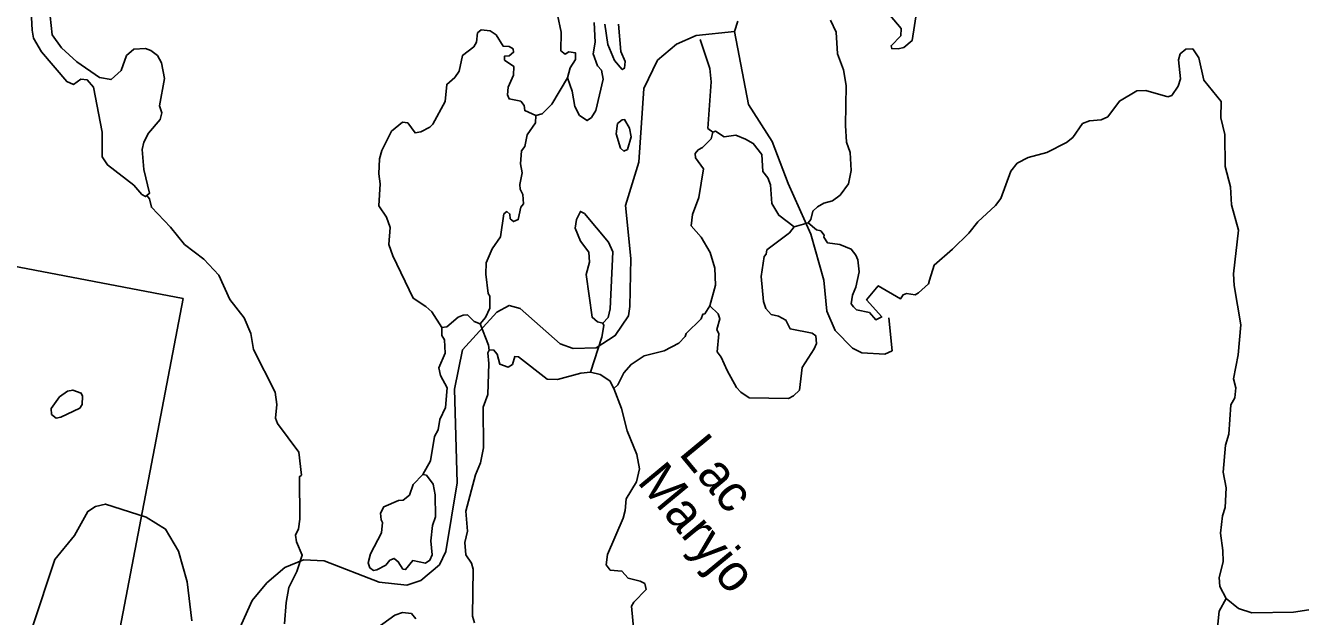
# Model space of a CAD drawing. Extents: x 347312 to 350503, y 6073086 to 6076432.
# Drawn here: x 349676.6 to 349803.4, y 6073953.1 to 6074011.8 of the extents above; entities that cross this region are included whole.
import ezdxf

# ---------------------------------------------------------------- set-up
doc = ezdxf.new("R2010")
doc.units = 0
doc.layers.add('Level 63', color=7, linetype='Continuous')

msp = doc.modelspace()

# ---------------------------------------------------------------- linework, layer by layer
at = {"layer": 'Level 63'}
for p, q in [((349747.4, 6074012.26), (349747.07, 6074011.24)), ((349752.98, 6073991.83), (349754.39, 6073992.24))]:
    msp.add_line(p, q, dxfattribs=at)
for points in [[(349677.13, 6074014.56), (349677.27, 6074011.36), (349677.42, 6074010.56), (349678.21, 6074009.22), (349680.71, 6074006.27), (349681.37, 6074005.98), (349682.1, 6074006.5), (349682.75, 6074006.42), (349683.37, 6074005.71), (349684.24, 6074001.25), (349684.25, 6073998.77), (349684.77, 6073997.98), (349687.38, 6073995.98), (349688.18, 6073995.04), (349688.55, 6073994.84), (349688.68, 6073994.95)], [(349765.18, 6074013.31), (349764.71, 6074010.33), (349763.9, 6074009.64), (349763.31, 6074009.5), (349762.68, 6074009.54), (349762.62, 6074009.82), (349763.58, 6074010.8), (349763.61, 6074011.52), (349760.5, 6074015.24)], [(349688.68, 6073994.95), (349688.95, 6073995.16), (349688.38, 6073997.53), (349688.22, 6073999.51), (349688.39, 6074000.25), (349688.83, 6074001.14), (349689.99, 6074002.49), (349690.16, 6074003.16), (349689.94, 6074003.86), (349690.44, 6074006.58), (349690.13, 6074008.13), (349689.73, 6074008.85), (349689.06, 6074009.35), (349688.54, 6074009.53), (349687.38, 6074009.48), (349686.64, 6074008.84), (349686.13, 6074007.36), (349685.12, 6074006.45), (349683.97, 6074006.67), (349681.72, 6074008.21), (349680.19, 6074009.6), (349679.28, 6074010.89), (349678.97, 6074013.68)], [(349729.49, 6074012.9), (349729.83, 6074011.16), (349729.82, 6074009.32), (349730.24, 6074008.99), (349730.6, 6074009.23), (349731.28, 6074009.11), (349731.27, 6074008.45), (349730.72, 6074007.64)], [(349730.72, 6074007.64), (349730.48, 6074006.63), (349730.93, 6074005.31), (349731.21, 6074003.79), (349731.65, 6074002.89), (349732.44, 6074002.38), (349732.84, 6074002.69), (349733.28, 6074003.37), (349734.01, 6074006.5), (349733.84, 6074007.39), (349733.44, 6074007.83), (349733.03, 6074009.03), (349733.22, 6074010.16), (349733.12, 6074012.14)], [(349734.19, 6074011.96), (349734.47, 6074009.95), (349735.13, 6074008.36), (349735.91, 6074007.45), (349736.13, 6074007.58), (349736.21, 6074008.24), (349735.78, 6074009.26), (349735.55, 6074011.95)], [(349756.59, 6074012.37), (349757.15, 6074011.18), (349757.29, 6074009.02), (349757.89, 6074007.43), (349758.16, 6074005.86), (349758.09, 6074001.9), (349758.2, 6074000.25), (349758.54, 6073999.21), (349758.66, 6073997.41), (349758.39, 6073996.11), (349757.56, 6073994.96), (349756.8, 6073994.42), (349755.95, 6073994.18)], [(349747.07, 6074011.24), (349743.27, 6074010.84), (349741.29, 6074009.98), (349739.41, 6074008.38), (349738.05, 6074005.57), (349737.56, 6073998.24), (349736.24, 6073993.94), (349736.75, 6073988.7), (349736.67, 6073983.92), (349736.53, 6073983), (349735.22, 6073981.03), (349733.31, 6073979.8), (349731.04, 6073979.74), (349729.73, 6073980.22), (349725.78, 6073983.71), (349724.66, 6073984.02), (349723.46, 6073983.35), (349720.03, 6073979.6), (349719.24, 6073975.72), (349719.51, 6073966.39), (349718.39, 6073959.59), (349717.75, 6073958.27), (349715.9, 6073956.7), (349714.51, 6073956.25), (349711.76, 6073956.52), (349706.28, 6073958.64), (349704.24, 6073958.76), (349702.39, 6073958), (349700.58, 6073956.46), (349699.13, 6073954.72), (349697.49, 6073951.03)], [(349721.2, 6073982.43), (349721.78, 6073982.18), (349722.31, 6073982.81), (349722.75, 6073983.76), (349722.74, 6073984.94), (349722.59, 6073985.2), (349722.36, 6073987.14), (349722.4, 6073988.26), (349722.98, 6073989.64), (349723.82, 6073990.85), (349724.15, 6073993.11), (349724.45, 6073993.35), (349724.75, 6073993.1), (349724.79, 6073992.64), (349725.12, 6073992.36), (349725.57, 6073992.55), (349725.83, 6073993.79), (349726.11, 6073994.12), (349726.04, 6073995.04), (349725.77, 6073995.58), (349725.73, 6073996.04), (349725.96, 6073997.2), (349725.79, 6073998.1), (349725.91, 6073999.38), (349726.23, 6073999.8), (349726.46, 6074000.96), (349727.29, 6074002.16), (349727.32, 6074002.88), (349726.22, 6074003.38), (349726.16, 6074003.87), (349725.82, 6074004.3), (349724.66, 6074004.53), (349724.5, 6074004.94), (349724.56, 6074005.69), (349725.12, 6074006.9), (349725.13, 6074007.77), (349724.2, 6074008.4), (349724.22, 6074008.79), (349724.68, 6074008.83), (349725.11, 6074009.17), (349725.06, 6074009.51), (349724.66, 6074009.74), (349724.09, 6074009.77), (349723.37, 6074010.89), (349722.79, 6074011.29), (349721.89, 6074011.39), (349721.52, 6074011.1), (349721.44, 6074010.17), (349721.15, 6074009.72), (349720.05, 6074008.85), (349719.71, 6074007.29), (349719.28, 6074006.67), (349718.47, 6074005.98), (349718.3, 6074004.27), (349717.1, 6074002.02), (349716.79, 6074001.72), (349715.89, 6074001.28), (349715.33, 6074001.16), (349714.6, 6074002.16), (349714.06, 6074002.22), (349712.99, 6074001.32), (349712.01, 6073999.4), (349711.79, 6073998.58), (349711.71, 6073997.1), (349711.86, 6073996.09), (349711.73, 6073993.92), (349712.48, 6073992.78), (349712.84, 6073991.76), (349712.71, 6073990.08), (349713.12, 6073988.94), (349715.14, 6073984.74), (349716.38, 6073983.93), (349716.98, 6073983.38), (349717.98, 6073981.83), (349718.48, 6073981.9), (349719.62, 6073982.86), (349720.1, 6073983.07), (349720.52, 6073983.08), (349721.2, 6073982.43)], [(349747.07, 6074011.24), (349748.46, 6074003.99), (349750.79, 6074000.3), (349752.39, 6073996.14)], [(349743.64, 6074010.43), (349744.61, 6074007.56), (349744.73, 6074006.24), (349744.43, 6074001.61), (349744.9, 6074001.23)], [(349790.13, 6074004.73), (349790.51, 6074004.87), (349791.14, 6074005.79), (349791.37, 6074006.52), (349791.17, 6074008.42), (349791.36, 6074009.01), (349791.9, 6074009.49), (349792.6, 6074009.5), (349793.19, 6074008.61), (349793.69, 6074006.4), (349795.41, 6074004.29), (349795.4, 6074002.66), (349795.79, 6074001.01), (349795.81, 6073997.83), (349796.33, 6073995.8), (349796.45, 6073994), (349797.13, 6073991.49), (349796.65, 6073987.16), (349796.7, 6073986), (349797.36, 6073982.08), (349797.11, 6073979.11), (349796.65, 6073976.74), (349796.88, 6073975.84), (349796.79, 6073974.85), (349796.38, 6073974.14), (349796.19, 6073971.22), (349795.85, 6073970.14), (349795.63, 6073967.47), (349795.9, 6073965.89), (349795.82, 6073963.94), (349795.54, 6073963.12), (349795.34, 6073961.39), (349795.6, 6073959.69), (349795.62, 6073958.57), (349795.22, 6073957.01), (349795.27, 6073956.12), (349795.92, 6073954.9), (349797.13, 6073953.91), (349798.45, 6073953.48), (349802.61, 6073953.57), (349804.12, 6073953.79)], [(349730.48, 6074006.63), (349728.93, 6074004), (349727.94, 6074003.05), (349727.32, 6074002.88)], [(349755.95, 6073994.18), (349755.3, 6073993.83), (349754.83, 6073993.4), (349754.64, 6073992.55), (349754.39, 6073992.24), (349755.22, 6073991.54), (349755.63, 6073991.43), (349755.97, 6073991), (349755.95, 6073990.82), (349756.31, 6073990.23), (349757.53, 6073990.06), (349758.66, 6073989.6), (349759.11, 6073989.03), (349759.32, 6073988.55), (349759.45, 6073987.35), (349759.13, 6073985.85), (349758.79, 6073985.04), (349758.66, 6073984.17), (349758.9, 6073983.87), (349759.17, 6073983.6), (349760.47, 6073983.33), (349761.11, 6073982.59), (349761.69, 6073982.88), (349760.19, 6073984.57), (349761.35, 6073985.98), (349763.57, 6073984.69), (349763.82, 6073985.06), (349764.14, 6073985.2), (349765, 6073985.07), (349765.33, 6073985.27), (349766.34, 6073986.18), (349766.45, 6073986.54), (349766.89, 6073988.03), (349768.74, 6073989.6), (349770.35, 6073991.2), (349771.24, 6073992.34), (349773.01, 6073993.95), (349773.54, 6073994.64), (349774.53, 6073997.37), (349775.16, 6073998.15), (349776.23, 6073998.72), (349778.1, 6073999.23), (349780.04, 6074000.21), (349780.67, 6074000.71), (349781.65, 6074002.08), (349782.35, 6074002.37), (349783.48, 6074002.45), (349784.15, 6074002.76), (349785.3, 6074004.32), (349787.05, 6074005.33), (349787.94, 6074005.38), (349790.13, 6074004.73)], [(349736.62, 6074001.62), (349736.14, 6074002.49), (349735.9, 6074002.46), (349735.43, 6074002.09), (349735.31, 6074001.07), (349735.75, 6073999.63), (349736.08, 6073999.35), (349736.43, 6073999.52), (349736.79, 6074000.78), (349736.62, 6074001.62)], [(349744.61, 6073983.97), (349745.43, 6073983.2), (349745.62, 6073982.7), (349745.31, 6073981.64), (349745.5, 6073981.2), (349745.35, 6073979.4), (349745.75, 6073978.9), (349746.32, 6073977.56), (349747.27, 6073975.87), (349747.7, 6073975.4), (349748.52, 6073974.85), (349752.42, 6073974.79), (349752.93, 6073975.03), (349753.51, 6073975.6), (349753.77, 6073977.87), (349754.99, 6073979.7), (349755.2, 6073980.25), (349755.14, 6073981.01), (349754.78, 6073981.27), (349752.59, 6073981.7), (349752.17, 6073982.57), (349751.43, 6073982.96), (349750.69, 6073983.13), (349750.19, 6073983.71), (349749.96, 6073984.4), (349749.71, 6073986.91), (349750, 6073988.88), (349750.21, 6073989.1), (349750.29, 6073989.54), (349752.52, 6073991.25), (349752.98, 6073991.83), (349751.48, 6073992.98), (349750.77, 6073994.15), (349750.65, 6073996.01), (349750.37, 6073996.71), (349749.87, 6073997.34), (349749.79, 6073999.02), (349748.92, 6074000.12), (349748.15, 6074000.54), (349747.2, 6074000.93), (349746.03, 6074000.76), (349745.19, 6074001.34), (349744.9, 6074001.23), (349744.76, 6074000.58), (349743.88, 6073999.71), (349743.46, 6073999.49), (349743.17, 6073999.1), (349743.18, 6073998.67), (349743.99, 6073997.58), (349743.51, 6073994.76), (349742.89, 6073993.07), (349742.76, 6073991.94), (349743.75, 6073990.82), (349744.63, 6073989.29), (349745.11, 6073987.72), (349745.16, 6073986.02), (349744.61, 6073983.97)], [(349680.34, 6073922.31), (349692.28, 6073984.7), (349619.96, 6073998.53), (349601.59, 6073902.48), (349673.91, 6073888.65), (349677.31, 6073906.44)], [(349752.39, 6073996.14), (349754.65, 6073991.09), (349755.94, 6073986.52), (349756.24, 6073983.46), (349757.05, 6073981.54), (349758.78, 6073979.77), (349759.73, 6073979.32), (349762.01, 6073979.18), (349762.72, 6073979.52), (349762.41, 6073982.8)], [(349688.68, 6073994.95), (349688.95, 6073994.61), (349689.12, 6073993.78), (349691.01, 6073991.8), (349692.42, 6073990.09), (349694.34, 6073988.62), (349695.82, 6073987.03), (349696.92, 6073984.6), (349698.35, 6073982.79), (349698.99, 6073981.24), (349699.28, 6073979.63), (349701.43, 6073975.41), (349701.58, 6073974.18), (349701.46, 6073972.83), (349701.67, 6073972.29), (349703.76, 6073969.44), (349704.04, 6073967.17), (349703.84, 6073967.01), (349703.86, 6073962.8), (349703.75, 6073961.84), (349703.43, 6073961.21), (349703.54, 6073960.53), (349704.11, 6073959.2), (349703.59, 6073957.59), (349702.79, 6073955.99), (349702.53, 6073954.53), (349702.34, 6073952.38)], [(349733.97, 6073982.27), (349734.51, 6073982.81), (349734.7, 6073983.67), (349734.98, 6073989.36), (349734.54, 6073990.32), (349732.15, 6073993.14), (349731.75, 6073993.37), (349731.35, 6073992.57), (349731.22, 6073991.71), (349731.77, 6073990.4), (349732.58, 6073989.31), (349732.64, 6073988.33), (349732.32, 6073987.1), (349732.91, 6073982.85), (349733.44, 6073982.39), (349733.97, 6073982.27)], [(349744.61, 6073983.97), (349744.13, 6073983.2), (349743.91, 6073983.14), (349743.74, 6073982.68), (349742.27, 6073981.24), (349742.17, 6073980.95), (349741.52, 6073980.27), (349740.06, 6073979.5), (349738.1, 6073979.03), (349736.79, 6073978.16), (349736.08, 6073977.33), (349735.46, 6073976.13), (349735.09, 6073975.78)], [(349717.98, 6073981.83), (349717.98, 6073981.02), (349718.24, 6073980.62), (349718.32, 6073979.28), (349717.7, 6073977.81), (349717.85, 6073977.07), (349718.5, 6073975.84), (349718.36, 6073973.89), (349717.79, 6073972.68), (349717.62, 6073971.67), (349717.27, 6073971.02), (349716.86, 6073968.58), (349716.1, 6073967.22)], [(349721.78, 6073982.18), (349722.63, 6073980.08), (349722.69, 6073979.59)], [(349733.97, 6073982.27), (349734.09, 6073982.04), (349733.89, 6073980.86), (349732.76, 6073977.41)], [(349732.76, 6073977.41), (349731.78, 6073977.29), (349729.46, 6073976.65), (349728.44, 6073976.71), (349725.61, 6073978.92), (349725.25, 6073978.96), (349725.01, 6073978.17), (349724.58, 6073977.88), (349723.74, 6073978.2), (349723.49, 6073979.19), (349723.11, 6073979.6), (349722.69, 6073979.59), (349722.57, 6073979.33), (349722.66, 6073978.26), (349722.54, 6073975.19), (349722.09, 6073973.91), (349722.13, 6073969.87), (349721.84, 6073968.39), (349721.33, 6073967.18), (349720.37, 6073963.6), (349720.53, 6073961.61), (349720.28, 6073960.49), (349720.38, 6073959.26), (349720.94, 6073958.41), (349721.09, 6073957.82), (349721.03, 6073953.16), (349721.22, 6073952.5)], [(349737.06, 6073951.68), (349736.83, 6073954.16), (349737.06, 6073954.56), (349738.3, 6073955.81), (349738.15, 6073956.4), (349737.7, 6073956.64), (349736.49, 6073956.93), (349735.88, 6073957.64), (349734.71, 6073957.74), (349734.31, 6073958.24), (349734.46, 6073959.29), (349736, 6073962.89), (349736.21, 6073963.65), (349736.29, 6073964.8), (349737.33, 6073966.49), (349737.61, 6073967.79), (349737.35, 6073969.22), (349736.41, 6073971.57), (349735.85, 6073973.78), (349735.09, 6073975.78), (349734.66, 6073976.53), (349733.73, 6073977.15), (349732.76, 6073977.41)], [(349682.27, 6073975.01), (349682.15, 6073975.3), (349681.31, 6073975.61), (349680.78, 6073975.52), (349679.99, 6073974.94), (349679.16, 6073973.8), (349679.21, 6073973.19), (349679.65, 6073972.83), (349680.12, 6073972.93), (349682.01, 6073973.83), (349682.26, 6073974.19), (349682.27, 6073975.01)], [(349716.45, 6073967.17), (349716.1, 6073967.22), (349715.13, 6073966.24), (349714.77, 6073965.19), (349714.14, 6073964.69), (349713.68, 6073964.65), (349712.21, 6073964.03), (349711.9, 6073963.4), (349711.94, 6073962.73), (349712.09, 6073962.47), (349712, 6073961.42), (349710.88, 6073959.34), (349710.65, 6073958.46), (349710.84, 6073957.96), (349711.2, 6073957.7), (349711.54, 6073957.75), (349712.41, 6073958.23), (349712.83, 6073958.72), (349713.25, 6073958.89), (349713.66, 6073958.56), (349714.12, 6073957.84), (349714.39, 6073957.78), (349715.1, 6073958.67), (349716.37, 6073958.43), (349716.8, 6073958.71), (349717.02, 6073959.26), (349716.9, 6073960.64), (349717.05, 6073962.17), (349717.34, 6073963.04), (349717.31, 6073965.2), (349717.11, 6073966.28), (349716.45, 6073967.17)], [(349670.29, 6073937.76), (349671.84, 6073937.31), (349672.81, 6073938.62), (349679.53, 6073958.79), (349681.5, 6073961.17), (349682.81, 6073963.56), (349683.56, 6073964.05), (349684.56, 6073964.29), (349688.62, 6073963), (349690.54, 6073961.81), (349691.83, 6073959.63), (349692.68, 6073956.56), (349693.14, 6073952.69)], [(349775.43, 6073941.51), (349776.37, 6073942.31), (349778, 6073942.79), (349778.54, 6073942.24), (349778.6, 6073941.75), (349779.08, 6073941.21), (349780.83, 6073940.31), (349781.71, 6073939.54), (349783.37, 6073937.43), (349784.42, 6073937.34), (349784.96, 6073937.55), (349790.95, 6073943.97), (349792.63, 6073945.2), (349793.63, 6073945.72), (349793.94, 6073945.74), (349795.3, 6073946.76), (349795.87, 6073947.48), (349796.17, 6073947.99), (349796.3, 6073948.86), (349796.13, 6073949.97), (349795.62, 6073951.3), (349795.04, 6073952.03), (349795.23, 6073953.65), (349795.92, 6073954.9)], [(349715.39, 6073952.88), (349714.97, 6073953.41), (349714.07, 6073953.52), (349713.31, 6073953.24), (349710.34, 6073951.11)]]:
    msp.add_lwpolyline(points, dxfattribs=at)

# ---------------------------------------------------------------- texts
for s, p in [('Lac ', (349741.45, 6073969.28)), ('Maryjo', (349737.31, 6073966.48))]:
    msp.add_text(s, height=3.667, rotation=309.568, dxfattribs=at).set_placement(p)

doc.saveas('drawing.dxf')
